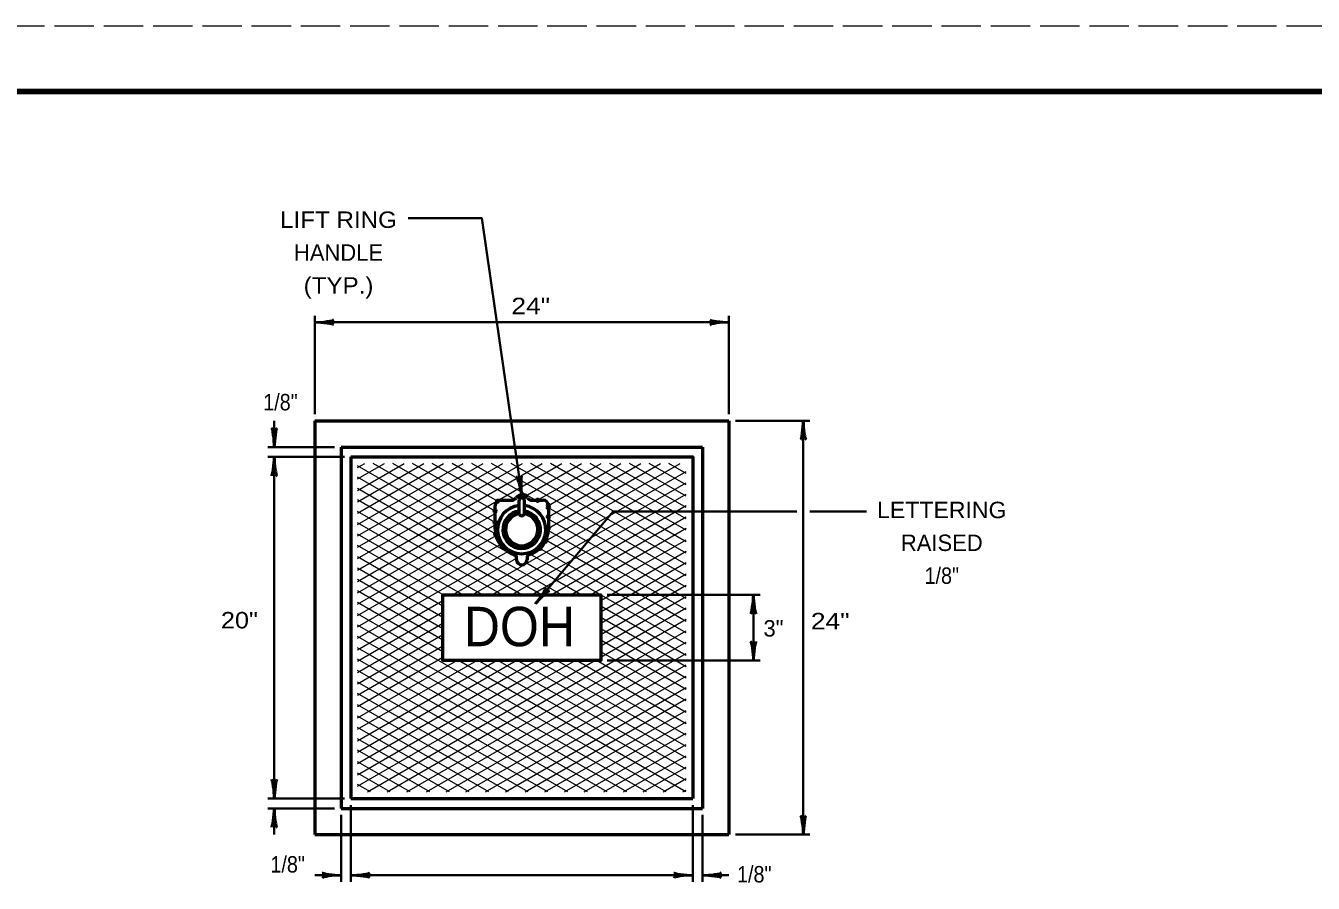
# Model space of a CAD drawing. Extents: x 788 to 1469, y -1 to 439.
# Drawn here: x 1076.7 to 1272.6, y 308.6 to 439.1 of the extents above; entities that cross this region are included whole.
import ezdxf
from ezdxf.enums import TextEntityAlignment as Align

# ---------------------------------------------------------------- set-up
doc = ezdxf.new("R2010")
doc.units = 0
doc.header["$PDMODE"] = 32
doc.header["$PDSIZE"] = 0.5
doc.linetypes.add('LONG_DASHED', pattern=[7.5, 6, -1.5])
doc.layers.add('1', color=7, linetype='Continuous', lineweight=35)
doc.layers.add('61', color=7, linetype='Continuous', lineweight=35)

msp = doc.modelspace()

# ---------------------------------------------------------------- linework, layer by layer
at = {"layer": '1'}
for p, q in [((1120.652, 379.952), (1120.652, 394.94)), ((1120.652, 393.94), (1183.652, 393.94)), ((1183.652, 379.952), (1183.652, 394.94)), ((1114.473, 378.952), (1114.473, 374.952)), ((1184.652, 378.952), (1195.986, 378.952)), ((1194.986, 378.952), (1194.986, 315.952)), ((1123.652, 374.952), (1113.473, 374.952)), ((1125.152, 373.452), (1113.473, 373.452)), ((1114.473, 373.452), (1114.473, 321.452)), ((1154.233, 351.111), (1166.042, 365.153)), ((1166.042, 365.153), (1193.986, 365.153)), ((1195.986, 365.153), (1204.587, 365.153)), ((1165.152, 352.452), (1188.401, 352.452)), ((1187.401, 352.452), (1187.401, 342.452)), ((1165.152, 342.452), (1188.401, 342.452)), ((1125.152, 321.452), (1113.473, 321.452)), ((1123.652, 319.952), (1113.473, 319.952)), ((1114.473, 319.952), (1114.473, 315.952)), ((1126.152, 320.452), (1126.152, 308.773)), ((1178.152, 320.452), (1178.152, 308.773)), ((1124.652, 318.952), (1124.652, 308.773)), ((1179.652, 318.952), (1179.652, 308.773)), ((1184.652, 315.952), (1195.986, 315.952)), ((1120.652, 309.773), (1124.652, 309.773)), ((1126.152, 309.773), (1178.152, 309.773)), ((1179.652, 309.773), (1183.652, 309.773))]:
    msp.add_line(p, q, dxfattribs=at)
at = {"layer": '1', "lineweight": 53}
for p, q in [((1120.652, 378.952), (1120.652, 315.952)), ((1120.652, 378.952), (1183.652, 378.952)), ((1183.652, 378.952), (1183.652, 315.952)), ((1124.652, 374.952), (1124.652, 319.952)), ((1124.652, 374.952), (1179.652, 374.952)), ((1179.652, 374.952), (1179.652, 319.952)), ((1126.152, 373.452), (1126.152, 321.452)), ((1148.902, 366.855), (1148.901, 366.848)), ((1148.901, 366.848), (1150.618, 366.848)), ((1148.901, 366.848), (1150.618, 366.848)), ((1151.736, 364.855), (1151.736, 366.848)), ((1152.546, 364.855), (1152.546, 366.848)), ((1153.664, 366.848), (1155.381, 366.848)), ((1153.664, 366.848), (1155.381, 366.848)), ((1148.091, 362.474), (1148.091, 366.038)), ((1148.091, 362.474), (1148.091, 366.038)), ((1156.191, 366.038), (1156.191, 362.506)), ((1156.191, 366.038), (1156.191, 362.506)), ((1151.315, 357.808), (1151.315, 358.343)), ((1151.315, 357.808), (1151.315, 358.343)), ((1152.951, 358.343), (1152.951, 357.808)), ((1152.951, 358.343), (1152.951, 357.808)), ((1126.152, 321.452), (1178.152, 321.452)), ((1124.652, 319.952), (1179.652, 319.952)), ((1120.652, 315.952), (1183.652, 315.952))]:
    msp.add_line(p, q, dxfattribs=at)
at = {"layer": '1', "lineweight": 13}
for p, q in [((1127.152, 371.821), (1128.244, 372.452)), ((1127.152, 370.089), (1131.244, 372.452)), ((1127.152, 368.357), (1134.244, 372.452)), ((1127.152, 366.625), (1137.244, 372.452)), ((1127.152, 364.893), (1140.244, 372.452)), ((1127.152, 363.161), (1143.244, 372.452)), ((1127.152, 361.429), (1146.244, 372.452)), ((1127.152, 359.697), (1149.244, 372.452)), ((1127.152, 357.965), (1152.244, 372.452)), ((1127.152, 356.233), (1155.244, 372.452)), ((1127.152, 354.501), (1158.244, 372.452)), ((1148.178, 361.685), (1129.529, 372.452)), ((1148.091, 363.468), (1132.529, 372.452)), ((1148.091, 365.2), (1135.529, 372.452)), ((1148.469, 366.713), (1138.529, 372.452)), ((1151.016, 366.975), (1141.529, 372.452)), ((1154.236, 366.848), (1144.529, 372.452)), ((1177.152, 355.349), (1147.529, 372.452)), ((1177.152, 357.082), (1150.529, 372.452)), ((1152.649, 367.49), (1161.244, 372.452)), ((1177.152, 358.813), (1153.529, 372.452)), ((1154.537, 366.848), (1164.244, 372.452)), ((1155.726, 360.606), (1176.244, 372.452)), ((1156.188, 366.069), (1167.244, 372.452)), ((1156.191, 364.338), (1170.244, 372.452)), ((1156.191, 362.606), (1173.244, 372.452)), ((1177.152, 360.546), (1156.529, 372.452)), ((1177.152, 362.278), (1159.529, 372.452)), ((1177.152, 364.01), (1162.529, 372.452)), ((1177.152, 365.742), (1165.529, 372.452)), ((1177.152, 367.474), (1168.529, 372.452)), ((1177.152, 369.206), (1171.529, 372.452)), ((1177.152, 370.938), (1174.529, 372.452)), ((1151.315, 358.142), (1127.152, 372.093)), ((1158.17, 352.452), (1127.152, 370.361)), ((1144.603, 352.452), (1177.152, 371.244)), ((1155.17, 352.452), (1127.152, 368.628)), ((1147.603, 352.452), (1177.152, 369.512)), ((1152.17, 352.452), (1127.152, 366.896)), ((1150.603, 352.452), (1177.152, 367.78)), ((1149.17, 352.452), (1127.152, 365.164)), ((1127.152, 352.769), (1148.091, 364.858)), ((1153.603, 352.452), (1177.152, 366.048)), ((1177.152, 353.617), (1156.191, 365.719)), ((1146.17, 352.452), (1127.152, 363.432)), ((1127.152, 351.037), (1148.091, 363.126)), ((1177.152, 351.885), (1156.191, 363.987)), ((1156.603, 352.452), (1177.152, 364.316)), ((1159.603, 352.452), (1177.152, 362.584)), ((1143.17, 352.452), (1127.152, 361.7)), ((1127.152, 349.305), (1148.223, 361.47)), ((1177.152, 348.421), (1155.792, 360.753)), ((1177.152, 350.153), (1156.171, 362.267)), ((1162.603, 352.452), (1177.152, 360.852)), ((1127.152, 347.573), (1148.856, 360.103)), ((1140.17, 352.452), (1127.152, 359.968)), ((1127.152, 345.841), (1150.006, 359.036)), ((1177.152, 344.957), (1153.444, 358.645)), ((1177.152, 346.689), (1154.91, 359.53)), ((1164.152, 351.614), (1177.152, 359.12)), ((1140.152, 350.731), (1127.152, 358.236)), ((1141.603, 352.452), (1151.315, 358.059)), ((1161.17, 352.452), (1152.741, 357.318)), ((1164.152, 349.882), (1177.152, 357.388)), ((1140.152, 348.999), (1127.152, 356.504)), ((1140.152, 347.267), (1127.152, 354.772)), ((1164.152, 348.15), (1177.152, 355.656)), ((1140.152, 345.534), (1127.152, 353.04)), ((1164.152, 346.418), (1177.152, 353.924)), ((1127.152, 344.109), (1140.152, 351.614)), ((1140.152, 343.802), (1127.152, 351.308)), ((1164.152, 344.686), (1177.152, 352.191)), ((1127.152, 342.377), (1140.152, 349.882)), ((1174.132, 322.452), (1127.152, 349.576)), ((1177.152, 343.225), (1164.152, 350.731)), ((1164.152, 342.954), (1177.152, 350.459)), ((1177.152, 341.493), (1164.152, 348.999)), ((1127.152, 340.644), (1140.152, 348.15)), ((1171.132, 322.452), (1127.152, 347.844)), ((1131.642, 322.452), (1177.152, 348.727)), ((1134.642, 322.452), (1177.152, 346.995)), ((1177.152, 339.761), (1164.152, 347.267)), ((1127.152, 338.912), (1140.152, 346.418)), ((1168.132, 322.452), (1127.152, 346.112)), ((1137.642, 322.452), (1177.152, 345.263)), ((1177.152, 338.029), (1164.152, 345.534)), ((1127.152, 337.18), (1140.152, 344.686)), ((1165.132, 322.452), (1127.152, 344.38)), ((1127.152, 335.448), (1140.152, 342.954)), ((1140.642, 322.452), (1177.152, 343.531)), ((1177.152, 336.297), (1164.152, 343.802)), ((1162.132, 322.452), (1127.152, 342.648)), ((1127.152, 333.716), (1142.283, 342.452)), ((1127.152, 331.984), (1145.283, 342.452)), ((1127.152, 330.252), (1148.283, 342.452)), ((1127.152, 328.52), (1151.283, 342.452)), ((1127.152, 326.788), (1154.283, 342.452)), ((1127.152, 325.056), (1157.283, 342.452)), ((1127.152, 323.324), (1160.283, 342.452)), ((1128.642, 322.452), (1163.283, 342.452)), ((1177.132, 322.452), (1142.491, 342.452)), ((1143.642, 322.452), (1177.152, 341.799)), ((1177.152, 324.173), (1145.491, 342.452)), ((1177.152, 325.905), (1148.491, 342.452)), ((1177.152, 327.637), (1151.491, 342.452)), ((1177.152, 329.369), (1154.491, 342.452)), ((1177.152, 331.101), (1157.491, 342.452)), ((1177.152, 332.833), (1160.491, 342.452)), ((1177.152, 334.565), (1163.491, 342.452)), ((1159.132, 322.452), (1127.152, 340.916)), ((1156.132, 322.452), (1127.152, 339.184)), ((1146.642, 322.452), (1177.152, 340.067)), ((1153.132, 322.452), (1127.152, 337.452)), ((1149.642, 322.452), (1177.152, 338.335)), ((1150.132, 322.452), (1127.152, 335.719)), ((1152.642, 322.452), (1177.152, 336.603)), ((1147.132, 322.452), (1127.152, 333.988)), ((1155.642, 322.452), (1177.152, 334.871)), ((1158.642, 322.452), (1177.152, 333.139)), ((1144.132, 322.452), (1127.152, 332.255)), ((1161.642, 322.452), (1177.152, 331.407)), ((1141.132, 322.452), (1127.152, 330.523)), ((1164.642, 322.452), (1177.152, 329.675)), ((1138.132, 322.452), (1127.152, 328.791)), ((1167.642, 322.452), (1177.152, 327.943)), ((1135.132, 322.452), (1127.152, 327.059)), ((1132.132, 322.452), (1127.152, 325.327)), ((1170.642, 322.452), (1177.152, 326.211)), ((1129.132, 322.452), (1127.152, 323.595)), ((1173.642, 322.452), (1177.152, 324.479)), ((1176.642, 322.452), (1177.152, 322.747))]:
    msp.add_line(p, q, dxfattribs=at)
at = {"layer": '1'}
msp.add_lwpolyline([(1152.138, 367.637), (1146.044, 409.803), (1134.873, 409.803)], dxfattribs=at)
at = {"layer": '1', "lineweight": 53}
msp.add_lwpolyline([(1126.152, 373.452), (1178.152, 373.452), (1178.152, 321.452)], dxfattribs=at)
msp.add_lwpolyline([(1140.152, 352.452), (1164.152, 352.452), (1164.152, 342.452), (1140.152, 342.452)], close=True, dxfattribs=at)
for centre, radius, start, end in [((1148.902, 366.038), 0.817, 90, 180), ((1148.902, 366.038), 0.817, 90, 180), ((1150.616, 367.671), 0.817, 270, 324.40119), ((1150.616, 367.671), 0.817, 270, 324.40119), ((1152.138, 366.582), 1.055, 35.59881, 144.40119), ((1152.138, 366.582), 1.055, 35.59881, 144.40119), ((1152.138, 366.82), 0.408, 4.83802, 175.16198), ((1153.66, 367.671), 0.817, 215.59881, 270), ((1153.66, 367.671), 0.817, 215.59881, 270), ((1155.373, 366.038), 0.817, 0, 90), ((1155.373, 366.038), 0.817, 0, 90), ((1152.129, 362.382), 3.674, 96.21818, 83.50424), ((1152.129, 362.382), 2.858, 98.00514, 81.63652), ((1152.129, 362.382), 2.449, 99.14766, 80.4482), ((1152.138, 364.891), 0.408, 184.83802, 355.16198), ((1152.138, 362.471), 4.052, 283.87448, 0.55336), ((1152.138, 362.471), 4.052, 283.87448, 0.55336), ((1152.138, 362.471), 4.052, 180, 256.12552), ((1152.138, 362.471), 4.052, 180, 256.12552), ((1151.117, 358.34), 0.204, 0, 76.12552), ((1151.117, 358.34), 0.204, 0, 76.12552), ((1152.138, 357.853), 0.818, 183.23003, 356.76998), ((1152.138, 357.853), 0.818, 183.23003, 356.76998), ((1153.158, 358.34), 0.204, 103.87448, 180), ((1153.158, 358.34), 0.204, 103.87448, 180)]:
    msp.add_arc(centre, radius, start, end, dxfattribs=at)
at = {"layer": '1', "lineweight": 40}
for centre, major_axis, ratio, start_param, end_param in [((1121.772, 393.728), (-1.756, 0.176), 0.07063, 3.1407148, 5.41811), ((1121.772, 393.728), (-1.756, 0.176), 0.07063, 3.1407148, 5.41811), ((1121.743, 394.216), (-1.786, -0.156), 0.122415, 0.8963533, 3.1415927), ((1121.743, 394.216), (-1.786, -0.156), 0.122415, 0.8963533, 3.1415927), ((1182.561, 393.663), (1.786, 0.156), 0.122415, 0.8963533, 3.1415927), ((1182.531, 394.151), (1.756, -0.176), 0.07063, 3.1407148, 5.41811), ((1194.775, 377.832), (0.176, 1.756), 0.07063, 3.1407148, 5.41811), ((1194.775, 377.832), (0.176, 1.756), 0.07063, 3.1407148, 5.41811), ((1195.263, 377.861), (-0.156, 1.786), 0.122415, 0.8963533, 3.1415927), ((1195.263, 377.861), (-0.156, 1.786), 0.122415, 0.8963533, 3.1415927), ((1114.196, 376.043), (0.156, -1.786), 0.122415, 0.8963533, 3.1415927), ((1114.684, 376.073), (-0.176, -1.756), 0.07063, 3.1407148, 5.41811), ((1114.261, 372.332), (0.176, 1.756), 0.07063, 3.1407148, 5.41811), ((1114.261, 372.332), (0.176, 1.756), 0.07063, 3.1407148, 5.41811), ((1114.749, 372.361), (-0.156, 1.786), 0.122415, 0.8963533, 3.1415927), ((1114.749, 372.361), (-0.156, 1.786), 0.122415, 0.8963533, 3.1415927), ((1151.708, 368.677), (0.41, -1.745), 0.122415, 0.8963533, 3.1415927), ((1152.187, 368.776), (0.077, -1.764), 0.07063, 3.1407148, 5.41811), ((1154.724, 352.124), (-1.03, -1.467), 0.122415, 0.8963533, 3.1415927), ((1155.116, 351.833), (-1.265, -1.231), 0.07063, 3.1407148, 5.41811), ((1187.19, 351.332), (0.176, 1.756), 0.07063, 3.1407148, 5.41811), ((1187.19, 351.332), (0.176, 1.756), 0.07063, 3.1407148, 5.41811), ((1187.677, 351.361), (-0.156, 1.786), 0.122415, 0.8963533, 3.1415927), ((1187.677, 351.361), (-0.156, 1.786), 0.122415, 0.8963533, 3.1415927), ((1187.125, 343.543), (0.156, -1.786), 0.122415, 0.8963533, 3.1415927), ((1187.613, 343.573), (-0.176, -1.756), 0.07063, 3.1407148, 5.41811), ((1114.196, 322.543), (0.156, -1.786), 0.122415, 0.8963533, 3.1415927), ((1114.196, 322.543), (0.156, -1.786), 0.122415, 0.8963533, 3.1415927), ((1114.684, 322.573), (-0.176, -1.756), 0.07063, 3.1407148, 5.41811), ((1114.684, 322.573), (-0.176, -1.756), 0.07063, 3.1407148, 5.41811), ((1114.261, 318.832), (0.176, 1.756), 0.07063, 3.1407148, 5.41811), ((1114.749, 318.861), (-0.156, 1.786), 0.122415, 0.8963533, 3.1415927), ((1194.71, 317.043), (0.156, -1.786), 0.122415, 0.8963533, 3.1415927), ((1195.198, 317.073), (-0.176, -1.756), 0.07063, 3.1407148, 5.41811), ((1123.561, 309.497), (1.786, 0.156), 0.122415, 0.8963533, 3.1415927), ((1123.531, 309.985), (1.756, -0.176), 0.07063, 3.1407148, 5.41811), ((1127.272, 309.561), (-1.756, 0.176), 0.07063, 3.1407148, 5.41811), ((1127.272, 309.561), (-1.756, 0.176), 0.07063, 3.1407148, 5.41811), ((1127.243, 310.049), (-1.786, -0.156), 0.122415, 0.8963533, 3.1415927), ((1127.243, 310.049), (-1.786, -0.156), 0.122415, 0.8963533, 3.1415927), ((1177.061, 309.497), (1.786, 0.156), 0.122415, 0.8963533, 3.1415927), ((1177.061, 309.497), (1.786, 0.156), 0.122415, 0.8963533, 3.1415927), ((1177.031, 309.985), (1.756, -0.176), 0.07063, 3.1407148, 5.41811), ((1177.031, 309.985), (1.756, -0.176), 0.07063, 3.1407148, 5.41811), ((1180.772, 309.561), (-1.756, 0.176), 0.07063, 3.1407148, 5.41811), ((1180.743, 310.049), (-1.786, -0.156), 0.122415, 0.8963533, 3.1415927)]:
    msp.add_ellipse(centre, major_axis=major_axis, ratio=ratio, start_param=start_param, end_param=end_param, dxfattribs=at)
at = {"layer": '1'}
for p in [(1148.469, 366.713), (1152.649, 367.49), (1154.537, 366.848), (1148.091, 365.2), (1156.188, 366.069), (1156.191, 365.719), (1156.191, 364.338), (1148.091, 363.468), (1156.191, 362.606), (1148.178, 361.685), (1155.726, 360.606), (1155.792, 360.753), (1154.91, 359.53)]:
    msp.add_point(p, dxfattribs=at)
at = {"layer": '61', "linetype": 'LONG_DASHED', "lineweight": 13}
msp.add_line((788.527, 439.076), (1468.547, 439.076), dxfattribs=at)
at = {"layer": '61', "lineweight": 158}
msp.add_lwpolyline([(1457.567, 429.076), (818.527, 429.076), (818.527, 9.056)], dxfattribs=at)

# ---------------------------------------------------------------- texts
at = {"layer": '1'}
for s, width, p in [('LIFT RING', 1.1, (1124.253, 408.304)), ('(TYP.)', 1.1, (1124.253, 398.304)), ('LETTERING', 1.05, (1216.066, 364.126)), ('1/8"', 0.9, (1216.066, 354.126))]:
    msp.add_text(s, height=2.5, dxfattribs=dict(at, width=width)).set_placement(p, align=Align.CENTER)
for s, p in [('HANDLE', (1124.254, 403.304)), ('RAISED', (1216.066, 359.126))]:
    msp.add_text(s, height=2.5, dxfattribs=at).set_placement(p, align=Align.CENTER)
for s, height, width, p in [('24"', 2.5, 1.2, (1150.56, 395.174)), ('1/8"', 2.5, 0.9, (1112.792, 380.533)), ('20"', 2.5, 1.15, (1106.349, 347.347)), ('DOH', 6, 0.95, (1143.313, 344.634)), ('24"', 2.5, 1.2, (1196.141, 347.21)), ('1/8"', 2.5, 0.9, (1113.888, 310.184)), ('1/8"', 2.5, 0.9, (1184.9, 308.675))]:
    msp.add_text(s, height=height, dxfattribs=dict(at, width=width)).set_placement(p)
msp.add_text('3"', height=2.5, dxfattribs=at).set_placement((1188.931, 346.106))

doc.saveas('drawing.dxf')
